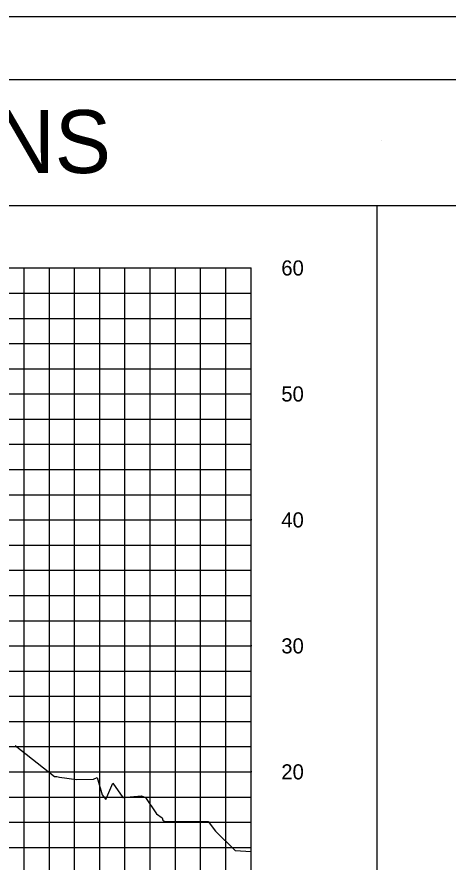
# Model space of a CAD drawing. Extents: x 2193008 to 2198143, y 1236112 to 1237864.
# Drawn here: x 2195004.3 to 2195038.5, y 1237270.9 to 1237338 of the extents above; entities that cross this region are included whole.
import ezdxf

# ---------------------------------------------------------------- set-up
doc = ezdxf.new("R2010")
doc.units = 0
for name, color, linetype in [('3', 7, 'Continuous'), ('31', 7, 'Continuous'), ('60', 7, 'Continuous'), ('ANNO-SHT', 7, 'Continuous'), ('DRAINAGE', 7, 'Continuous'), ('Level 1', 7, 'Continuous'), ('M-ROADS', 7, 'Continuous'), ('SHT-BNDRY', 7, 'Continuous')]:
    doc.layers.add(name, color=color, linetype=linetype)

# ---------------------------------------------------------------- blocks, each defined once
blk = doc.blocks.new('SC47208')
at = {"layer": 'Level 1'}
blk.add_line((0, 0), (0, 0), dxfattribs=at)

msp = doc.modelspace()

# ---------------------------------------------------------------- linework, layer by layer
msp.add_lwpolyline([(2194882.86, 1237133.046), (2195182.86, 1237133.046), (2195182.86, 1237323.046), (2194882.86, 1237323.046)], close=True)
at = {"layer": '3'}
msp.add_line((2195032.86, 1237228.046), (2195032.86, 1237323.046), dxfattribs=at)
at = {"layer": '60'}
for p, q in [((2195022.86, 1237258.106), (2195022.86, 1237318.106)), ((2195022.92, 1237298.106), (2195022.86, 1237298.106)), ((2195022.92, 1237288.106), (2195022.86, 1237288.106)), ((2195022.92, 1237278.106), (2195022.86, 1237278.106))]:
    msp.add_line(p, q, dxfattribs=at)
at = {"layer": 'M-ROADS'}
for p, q in [((2194892.86, 1237318.106), (2195022.86, 1237318.106)), ((2195004.86, 1237258.106), (2195004.86, 1237318.106)), ((2195006.86, 1237258.106), (2195006.86, 1237318.106)), ((2195008.86, 1237258.106), (2195008.86, 1237318.106)), ((2195010.86, 1237258.106), (2195010.86, 1237318.106)), ((2195012.86, 1237258.106), (2195012.86, 1237318.106)), ((2195014.86, 1237258.106), (2195014.86, 1237318.106)), ((2195016.86, 1237258.106), (2195016.86, 1237318.106)), ((2195018.86, 1237258.106), (2195018.86, 1237318.106)), ((2195020.86, 1237258.106), (2195020.86, 1237318.106)), ((2195022.86, 1237258.106), (2195022.86, 1237318.106)), ((2194892.86, 1237316.106), (2195022.86, 1237316.106)), ((2194892.86, 1237314.106), (2195022.86, 1237314.106)), ((2194892.86, 1237312.106), (2195022.86, 1237312.106)), ((2194892.86, 1237310.106), (2195022.86, 1237310.106)), ((2194892.86, 1237308.106), (2195022.86, 1237308.106)), ((2194892.86, 1237306.106), (2195022.86, 1237306.106)), ((2194892.86, 1237304.106), (2195022.86, 1237304.106)), ((2194892.86, 1237302.106), (2195022.86, 1237302.106)), ((2194892.86, 1237300.106), (2195022.86, 1237300.106)), ((2194892.86, 1237298.106), (2195022.86, 1237298.106)), ((2194892.86, 1237296.106), (2195022.86, 1237296.106)), ((2194892.86, 1237294.106), (2195022.86, 1237294.106)), ((2194892.86, 1237292.106), (2195022.86, 1237292.106)), ((2194892.86, 1237290.106), (2195022.86, 1237290.106)), ((2194892.86, 1237288.106), (2195022.86, 1237288.106)), ((2194892.86, 1237286.106), (2195022.86, 1237286.106)), ((2194892.86, 1237284.106), (2195022.86, 1237284.106)), ((2194892.86, 1237282.106), (2195022.86, 1237282.106)), ((2194892.86, 1237280.106), (2195022.86, 1237280.106)), ((2194892.86, 1237278.106), (2195022.86, 1237278.106)), ((2194892.86, 1237276.106), (2195022.86, 1237276.106)), ((2194892.86, 1237274.106), (2195022.86, 1237274.106)), ((2194892.86, 1237272.106), (2195022.86, 1237272.106))]:
    msp.add_line(p, q, dxfattribs=at)
msp.add_lwpolyline([(2194857.863, 1237118.036), (2195197.863, 1237118.036), (2195197.863, 1237338.036), (2194857.863, 1237338.036)], close=True, dxfattribs=at)
msp.add_lwpolyline([(2195004.137, 1237280.204), (2195007.265, 1237277.736), (2195007.45, 1237277.736), (2195007.657, 1237277.683), (2195009.023, 1237277.511), (2195010.356, 1237277.521), (2195010.648, 1237277.661), (2195011.042, 1237276.289), (2195011.341, 1237275.924), (2195011.894, 1237277.219), (2195012.686, 1237276.064), (2195012.738, 1237276.08), (2195013.282, 1237276.114), (2195014.172, 1237276.207), (2195014.498, 1237276.074), (2195015.372, 1237274.762), (2195015.799, 1237274.461), (2195015.868, 1237274.277), (2195016.026, 1237274.156), (2195018.563, 1237274.156), (2195019.45, 1237274.156), (2195020.044, 1237273.387), (2195021.596, 1237271.871), (2195022.86, 1237271.778)], dxfattribs=at)
at = {"layer": 'SHT-BNDRY'}
msp.add_lwpolyline([(2194870.363, 1237123.036), (2195192.863, 1237123.036), (2195192.863, 1237333.036), (2194870.363, 1237333.036)], close=True, dxfattribs=at)

# ---------------------------------------------------------------- block references
at = {"layer": 'DRAINAGE', "xscale": 0.20000000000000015, "yscale": 0.20000000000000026, "rotation": -116.41666666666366}
msp.add_blockref('SC47208', (2195033.181, 1237328.234), dxfattribs=at)
msp.add_blockref('SC47208', (2195033.181, 1237328.234), dxfattribs=at)

# ---------------------------------------------------------------- texts
at = {"layer": '31'}
for s, p in [('60', (2195025.26, 1237317.506)), ('50', (2195025.26, 1237307.506)), ('40', (2195025.26, 1237297.506)), ('30', (2195025.26, 1237287.506)), ('20', (2195025.26, 1237277.506))]:
    msp.add_text(s, height=1.2, dxfattribs=at).set_placement(p)
at = {"layer": 'ANNO-SHT'}
msp.add_text('              SIGN CROSS SECTIONS               ', height=4.9995, rotation=360, dxfattribs=at).set_placement((2194907.736, 1237325.638))

doc.saveas('drawing.dxf')
